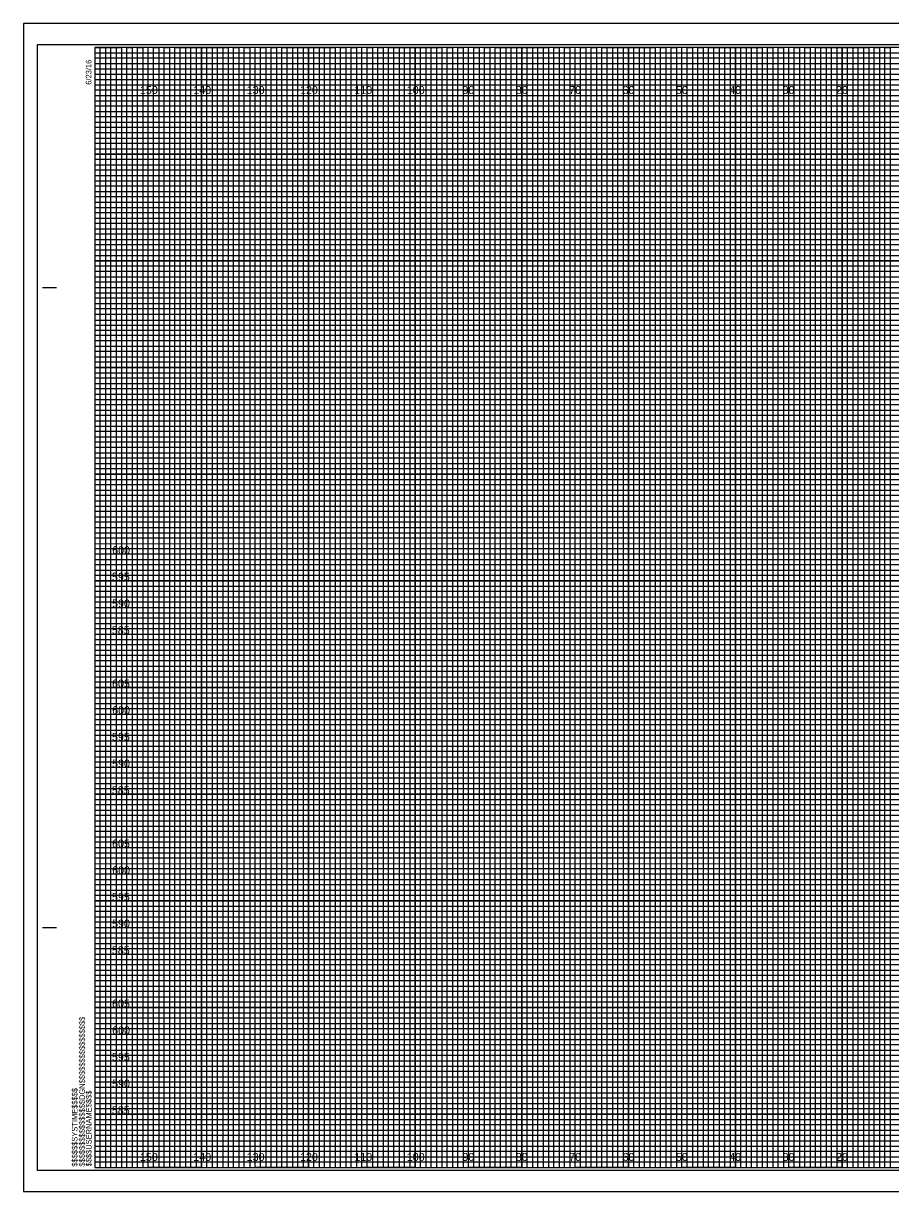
# Model space of a CAD drawing. Extents: x -13 to 323, y -5 to 215.
# Drawn here: x -13.4 to 149.1, y -4.5 to 214.5 of the extents above; entities that cross this region are included whole.
import ezdxf

# ---------------------------------------------------------------- set-up
doc = ezdxf.new("R2010")
doc.units = 0
for name, color, linetype in [('Exist Cross Section Cell', 7, 'Continuous'), ('Exist XS Center Line Elevation Label', 7, 'Continuous'), ('Exist XS Ground Line', 7, 'Continuous'), ('Prop XS Dump Level', 7, 'Continuous'), ('Prop XS Finish Grade', 7, 'Continuous'), ('Prop XS Finish Grade Earthwork', 7, 'Continuous'), ('Prop XS Hydro Elevations', 7, 'Continuous'), ('Prop XS Pvmt Edge Slope', 7, 'Continuous'), ('Prop XS SE Text', 7, 'Continuous'), ('Prop XS Side Slope Text', 7, 'Continuous'), ('Prop XS Subgrade Earthwork', 7, 'Continuous')]:
    doc.layers.add(name, color=color, linetype=linetype)

msp = doc.modelspace()

# ---------------------------------------------------------------- linework, layer by layer
at = {"layer": 'Exist Cross Section Cell'}
for points in [[(0, 210), (5, 210), (5, 0), (15, 0), (15, 210), (25, 210), (25, 0), (35, 0), (35, 210), (45, 210), (45, 0), (55, 0), (55, 210), (65, 210), (65, 0), (75, 0), (75, 210), (85, 210), (85, 0), (95, 0), (95, 210), (105, 210), (105, 0), (115, 0), (115, 210), (125, 210), (125, 0), (135, 0), (135, 210), (145, 210), (145, 0), (155, 0)], [(0, 205), (275, 205)], [(0, 185), (320, 185), (320, 195), (0, 195)], [(0, 165), (320, 165), (320, 175), (0, 175)], [(0, 145), (320, 145), (320, 155), (0, 155)], [(0, 125), (320, 125), (320, 135), (0, 135)], [(0, 105), (320, 105), (320, 115), (0, 115)], [(0, 85), (320, 85), (320, 95), (0, 95)], [(0, 65), (320, 65), (320, 75), (0, 75)], [(0, 45), (320, 45), (320, 55), (0, 55)], [(0, 25), (320, 25), (320, 35), (0, 35)], [(0, 5), (320, 5), (320, 15), (0, 15)]]:
    msp.add_lwpolyline(points, dxfattribs=at)
at = {"layer": 'Exist XS Center Line Elevation Label'}
for p, q in [((10, 210), (0, 210)), ((10, 0), (10, 210)), ((30, 210), (20, 210)), ((20, 210), (20, 0)), ((30, 0), (30, 210)), ((50, 210), (40, 210)), ((40, 210), (40, 0)), ((50, 0), (50, 210)), ((70, 210), (60, 210)), ((60, 210), (60, 0)), ((70, 0), (70, 210)), ((90, 210), (80, 210)), ((80, 210), (80, 0)), ((90, 0), (90, 210)), ((110, 210), (100, 210)), ((100, 210), (100, 0)), ((110, 0), (110, 210)), ((130, 210), (120, 210)), ((120, 210), (120, 0)), ((130, 0), (130, 210)), ((150, 210), (140, 210)), ((140, 210), (140, 0)), ((20, 0), (10, 0)), ((40, 0), (30, 0)), ((60, 0), (50, 0)), ((80, 0), (70, 0)), ((100, 0), (90, 0)), ((120, 0), (110, 0)), ((140, 0), (130, 0))]:
    msp.add_line(p, q, dxfattribs=at)
for points in [[(0, 200), (320, 200), (320, 190), (0, 190)], [(0, 180), (320, 180), (320, 170), (0, 170)], [(0, 160), (320, 160), (320, 150), (0, 150)], [(0, 140), (320, 140), (320, 130), (0, 130)], [(0, 120), (320, 120), (320, 110), (0, 110)], [(0, 100), (320, 100), (320, 90), (0, 90)], [(0, 80), (320, 80), (320, 70), (0, 70)], [(0, 60), (320, 60), (320, 50), (0, 50)], [(0, 40), (320, 40), (320, 30), (0, 30)], [(0, 20), (320, 20), (320, 10), (0, 10)]]:
    msp.add_lwpolyline(points, dxfattribs=at)
at = {"layer": 'Prop XS Dump Level'}
for p, q in [((0, 209), (260, 209)), ((260, 207.98), (0, 207.98)), ((0, 207.98), (0, 207)), ((0, 207), (260, 207)), ((260, 205.89), (0, 205.89)), ((0, 205.89), (0, 204)), ((0, 204), (320, 204))]:
    msp.add_line(p, q, dxfattribs=at)
for points in [[(0, 203), (270, 203), (320, 203), (320, 202), (0, 202)], [(0, 201), (320, 201), (320, 199), (0, 199)], [(0, 198), (320, 198), (320, 197), (0, 196.98)], [(0, 196), (320, 196), (320, 194), (0, 194)], [(0, 193), (320, 193), (320, 192), (0, 192)], [(0, 191), (320, 191), (320, 189), (0, 189)], [(0, 188), (320, 188), (320, 187), (0, 187)], [(0, 186), (320, 186), (320, 184), (0, 184)], [(0, 183), (320, 183), (320, 182), (0, 182)], [(0, 181), (320, 181), (320, 179), (0, 179)], [(0, 178), (320, 178), (320, 177), (0, 177)], [(0, 176), (320, 176), (320, 173.95), (320, 173), (320, 172), (0, 172)], [(0, 174), (320, 174), (320, 173), (0, 173)], [(0, 171), (320, 171), (320, 169), (0, 169.03)], [(0, 169.03), (320, 169), (320, 168), (0, 168)], [(0, 167), (320, 167), (320, 166), (0, 166)], [(0, 164), (320, 164), (320, 163), (0, 163)], [(0, 162), (320, 162), (320, 161), (0, 161)], [(-0.07, 158.89), (320, 158.89), (320, 157.88), (-0.07, 157.88)], [(0, 157), (320, 157), (320, 156), (0, 156)], [(0, 154), (320, 154), (320, 153), (0, 153)], [(0, 152), (320, 152), (320, 151), (0, 151)], [(0, 149), (320, 149), (320, 148), (0, 148)], [(0, 147), (320, 147), (320, 146), (0, 146)], [(0, 144), (320, 144), (320, 143), (0, 143)], [(0, 142), (320, 142), (320, 141), (0, 141)], [(0, 139), (320, 139), (319.99, 137.98), (0, 138)], [(0, 137), (320, 137), (320, 136), (0, 136)], [(0, 134), (320, 134), (320, 133), (0, 133)], [(0, 132), (320, 132), (320, 131), (0, 131)], [(0, 129), (320, 129), (320, 128), (0, 128)], [(0, 127), (320, 127), (320, 126), (0, 126)], [(0, 124), (320, 124), (320, 123), (0, 123)], [(0, 122), (320, 122), (320, 121), (0, 121)], [(0, 119), (320, 119), (320, 118), (0, 118)], [(0, 116.99), (320.07, 116.91), (320, 116), (0, 116)], [(0, 114), (320, 114), (320, 113), (0, 113)], [(0, 112), (320, 112), (320, 111), (0, 111)], [(0, 109), (320, 109), (320, 108), (0, 108)], [(0, 107), (320, 107), (320, 106), (0, 106)], [(0, 104), (320, 104), (320, 103), (0, 103)], [(0, 102), (320, 102), (320, 101), (0, 101)], [(0, 99), (320, 99), (320, 98), (0, 98)], [(0, 97), (320, 97), (320, 96), (0, 96)], [(0, 94), (320, 94), (320, 93), (0, 93)], [(0, 92), (320, 92), (320, 91), (0, 91)], [(0, 89), (320, 89), (320, 88), (0, 88)], [(0, 87), (320, 87), (320, 86), (0, 86)], [(0, 84), (320, 84), (320, 83), (0, 83)], [(0, 82), (320, 82), (320, 81), (0, 81)], [(0, 79), (320, 79), (319.99, 77.98), (0, 78)], [(0, 77), (320, 77), (320, 76), (0, 76)], [(0, 74), (320, 74), (320, 73), (0, 73)], [(0, 72), (320, 72), (320, 71), (0, 71)], [(0, 69), (320, 69), (320, 68), (0, 68)], [(0, 67), (320, 67), (320, 66), (0, 66)], [(0, 64), (320, 64), (320, 63), (0, 63)], [(0, 62), (320, 62), (320, 61), (0, 61)], [(0, 59), (320, 59), (320, 58), (0, 58)], [(0, 56.99), (320.07, 56.91), (320, 56), (0, 56)], [(0, 54), (320, 54), (320, 53), (0, 53)], [(0, 52), (320, 52), (320, 51), (0, 51)], [(0, 49), (320, 49), (320, 48), (0, 48)], [(0, 47), (320, 47), (320, 46), (0, 46)], [(0, 44), (320, 44), (320, 43), (0, 43)], [(0, 42), (320, 42), (320, 41), (0, 41)], [(0, 39), (320, 39), (320, 38), (0, 38)], [(0, 37), (320, 37), (320, 36), (0, 36)], [(0, 34), (320, 34), (320, 33), (0, 33)], [(0, 32), (320, 32), (320, 31), (0, 31)], [(0, 29), (320, 29), (320, 28), (0, 28)], [(0, 27), (320, 27), (320, 26), (0, 26)], [(0, 24), (320, 24), (320, 23), (0, 23)], [(0, 22), (320, 22), (320, 21), (0, 21)], [(0, 19), (320, 19), (320, 18), (0, 18)], [(0, 17), (320, 17), (320, 16), (0, 16)], [(0, 14), (320, 14), (320, 13), (0, 13)], [(0, 12), (320, 12), (320, 11), (0, 11)], [(0, 9), (320, 9), (320, 8), (0, 8)], [(0, 7), (320, 7), (320, 6), (0, 6)], [(0, 4), (320, 4), (320, 3), (0, 3)], [(0, 2), (320, 2), (320, 1), (0, 1)]]:
    msp.add_lwpolyline(points, dxfattribs=at)
at = {"layer": 'Prop XS Finish Grade'}
for p, q in [((323.3, 214.5), (-13.4, 214.5)), ((-13.4, 214.5), (-13.4, -4.5)), ((-13.4, -4.5), (323.3, -4.5))]:
    msp.add_line(p, q, dxfattribs=at)
at = {"layer": 'Prop XS Finish Grade Earthwork'}
msp.add_lwpolyline([(-10.8, -0.5), (322.4, -0.5), (322.4, 210.5), (-10.8, 210.5)], close=True, dxfattribs=at)
at = {"layer": 'Prop XS Hydro Elevations'}
for points in [[(0, 0), (1, 0), (1, 210), (2, 210), (2, 0)], [(2, 0), (3, 0), (3, 210), (4, 210), (4, 0)], [(5, 0), (6, 0), (6, 210), (7, 210), (7, 0)], [(7, 0), (8, 0), (8, 210), (9, 210), (9, 0)], [(10, 0), (11, 0), (11, 210), (12, 210), (12, 0)], [(12, 0), (13, 0), (13, 210), (14, 210), (14, 0)], [(15, 0), (16, 0), (16, 210), (17, 210), (17, 0)], [(17, 0), (18, 0), (18, 210), (19, 210), (19, 0)], [(20, 0), (21, 0), (21, 210), (22, 210), (22, 0)], [(22, 0), (23, 0), (23, 210), (24, 210), (24, 0)], [(25, 0), (26, 0), (26, 210), (27, 210), (27, 0)], [(27, 0), (28, 0), (28, 210), (29, 210), (29, 0)], [(30, 0), (31, 0), (31, 210), (32, 210), (32, 0)], [(32, 0), (33, 0), (33, 210), (34, 210), (34, 0)], [(35, 0), (36, 0), (36, 210), (37, 210), (37, 0)], [(37, 0), (38, 0), (38, 210), (39, 210), (39, 0)], [(40, 0), (41, 0), (41, 210), (42, 210), (42, 0)], [(42, 0), (43, 0), (43, 210), (44, 210), (44, 0)], [(45, 0), (46, 0), (46, 210), (47, 210), (47, 0)], [(47, 0), (48, 0), (48, 210), (49, 210), (49, 0)], [(50, 0), (51, 0), (51, 210), (52, 210), (52, 0)], [(52, 0), (53, 0), (53, 210), (54, 210), (54, 0)], [(55, 0), (56, 0), (56, 210), (57, 210), (57, 0)], [(57, 0), (58, 0), (58, 210), (59, 210), (59, 0)], [(60, 0), (61, 0), (61, 210), (62, 210), (62, 0)], [(62, 0), (63, 0), (63, 210), (64, 210), (64, 0)], [(65, 0), (66, 0), (66, 210), (67, 210), (67, 0)], [(67, 0), (68, 0), (68, 210), (69, 210), (69, 0)], [(70, 0), (71, 0), (71, 210), (72, 210), (72, 0)], [(72, 0), (73, 0), (73, 210), (74, 210), (74, 0)], [(75, 0), (76, 0), (76, 210), (77, 210), (77, 0)], [(77, 0), (78, 0), (78, 210), (79, 210), (79, 0)], [(80, 0), (81, 0), (81, 210), (82, 210), (82, 0)], [(82, 0), (83, 0), (83, 210), (84, 210), (84, 0)], [(85, 0), (86, 0), (86, 210), (87, 210), (87, 0)], [(87, 0), (88, 0), (88, 210), (89, 210), (89, 0)], [(90, 0), (91, 0), (91, 210), (92, 210), (92, 0)], [(92, 0), (93, 0), (93, 210), (94, 210), (94, 0)], [(95, 0), (96, 0), (96, 210), (97, 210), (97, 0)], [(97, 0), (98, 0), (98, 210), (99, 210), (99, 0)], [(100, 0), (101, 0), (101, 210), (102, 210), (102, 0)], [(102, 0), (103, 0), (103, 210), (104, 210), (104, 0)], [(105, 0), (106, 0), (106, 210), (107, 210), (107, 0)], [(107, 0), (108, 0), (108, 210), (109, 210), (109, 0)], [(110, 0), (111, 0), (111, 210), (112, 210), (112, 0)], [(112, 0), (113, 0), (113, 210), (114, 210), (114, 0)], [(115, 0), (116, 0), (116, 210), (117, 210), (117, 0)], [(117, 0), (118, 0), (118, 210), (119, 210), (119, 0)], [(120, 0), (121, 0), (121, 210), (122, 210), (122, 0)], [(122, 0), (123, 0), (123, 210), (124, 210), (124, 0)], [(125, 0), (126, 0), (126, 210), (127, 210), (127, 0)], [(127, 0), (128, 0), (128, 210), (129, 210), (129, 0)], [(130, 0), (131, 0), (131, 210), (132, 210), (132, 0)], [(132, 0), (133, 0), (133, 210), (134, 210), (134, 0)], [(135, 0), (136, 0), (136, 210), (137, 210), (137, 0)], [(137, 0), (138, 0), (138, 210), (139, 210), (139, 0)], [(140, 0), (141, 0), (141, 210), (142, 210), (142, 0)], [(142, 0), (143, 0), (143, 210), (144, 210), (144, 0)], [(145, 0), (146, 0), (146, 210), (147, 210), (147, 0)], [(147, 0), (148, 0), (148, 210), (149, 210), (149, 0)]]:
    msp.add_lwpolyline(points, dxfattribs=at)
at = {"layer": 'Prop XS Pvmt Edge Slope'}
for p, q in [((10, 0), (10, 210)), ((20, 0), (20, 210)), ((30, 0), (30, 210)), ((40, 0), (40, 210)), ((50, 0), (50, 210)), ((60, 0), (60, 210)), ((70, 0), (70, 210)), ((80, 0), (80, 210)), ((90, 0), (90, 210)), ((100, 0), (100, 210)), ((110, 0), (110, 210)), ((120, 0), (120, 210)), ((130, 0), (130, 210)), ((140, 0), (140, 210)), ((0, 200), (320, 200)), ((0, 190), (320, 190)), ((0, 180), (320, 180)), ((0, 170), (320, 170)), ((0, 160), (320, 160)), ((0, 150), (320, 150)), ((0, 140), (320, 140)), ((0, 130), (320, 130)), ((0, 120), (320, 120)), ((0, 110), (320, 110)), ((0, 100), (320, 100)), ((0, 90), (320, 90)), ((0, 80), (320, 80)), ((0, 70), (320, 70)), ((0, 60), (320, 60)), ((0, 50), (320, 50)), ((0, 40), (320, 40)), ((0, 30), (320, 30)), ((0, 20), (320, 20)), ((0, 10), (320, 10))]:
    msp.add_line(p, q, dxfattribs=at)
at = {"layer": 'Prop XS SE Text'}
for p, q in [((-9.8, 165), (-7.3, 165)), ((-9.7, 165), (-7.2, 165)), ((-9.8, 45), (-7.3, 45)), ((-9.7, 45), (-7.2, 45)), ((0, 0), (0, 0)), ((0, 0), (0, 0)), ((0, 0), (0, 0)), ((0, 0), (0, 0)), ((0, 0), (0, 0)), ((0, 0), (0, 0)), ((0, 0), (0, 0))]:
    msp.add_line(p, q, dxfattribs=at)
msp.add_lwpolyline([(320, 210), (0, 210), (0, 0), (320, 0)], close=True, dxfattribs=at)
at = {"layer": 'Prop XS Side Slope Text'}
msp.add_lwpolyline([(-13.4, -4.5), (323.3, -4.5), (323.3, 214.5), (-13.4, 214.5)], close=True, dxfattribs=at)

# ---------------------------------------------------------------- texts
at = {"layer": 'Exist XS Ground Line'}
for s, p in [('150', (8.44, 201.25)), ('140', (18.44, 201.25)), ('130', (28.44, 201.25)), ('120', (38.44, 201.25)), ('110', (48.62, 201.25)), ('100', (58.44, 201.25)), ('90', (68.86, 201.25)), ('80', (78.86, 201.25)), ('70', (88.86, 201.25)), ('60', (98.86, 201.25)), ('50', (108.86, 201.25)), ('40', (118.86, 201.25)), ('30', (128.86, 201.25)), ('20', (138.86, 201.25)), ('150', (8.44, 1.25)), ('140', (18.44, 1.25)), ('130', (28.44, 1.25)), ('120', (38.44, 1.25)), ('110', (48.62, 1.25)), ('100', (58.44, 1.25)), ('90', (68.86, 1.25)), ('80', (78.86, 1.25)), ('70', (88.86, 1.25)), ('60', (98.86, 1.25)), ('50', (108.86, 1.25)), ('40', (118.86, 1.25)), ('30', (128.86, 1.25)), ('20', (138.86, 1.25))]:
    msp.add_text(s, height=1.5, dxfattribs=at).set_placement(p)
at = {"layer": 'Prop XS SE Text'}
for s, p in [('6/23/16', (-0.65, 203)), ('$$$$$$$$$$$$$$$$DGN$$$$$$$$$$$$$$$$', (-1.88, 0.18)), ('$$$$$$SYSTIME$$$$$', (-3.26, 0.18)), ('$$$$USERNAME$$$$', (-0.62, 0.23))]:
    msp.add_text(s, height=1.05, rotation=90, dxfattribs=at).set_placement(p)
at = {"layer": 'Prop XS Subgrade Earthwork'}
for s, p in [('600', (3.24, 115)), ('595', (3.2, 110)), ('590', (3.22, 105)), ('585', (3.18, 100)), ('605', (3.22, 90)), ('600', (3.24, 85)), ('595', (3.2, 80)), ('590', (3.22, 75)), ('585', (3.18, 70)), ('605', (3.22, 60)), ('600', (3.24, 55)), ('595', (3.2, 50)), ('590', (3.22, 45)), ('585', (3.18, 40)), ('605', (3.22, 30)), ('600', (3.24, 25)), ('595', (3.2, 20)), ('590', (3.22, 15)), ('585', (3.18, 10))]:
    msp.add_text(s, height=1.5, dxfattribs=at).set_placement(p)

doc.saveas('drawing.dxf')
